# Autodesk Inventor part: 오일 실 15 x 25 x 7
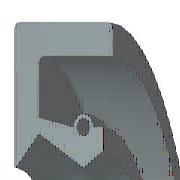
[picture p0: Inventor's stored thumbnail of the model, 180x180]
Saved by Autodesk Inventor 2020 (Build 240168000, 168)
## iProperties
Created: 2012-02
Part Number: 오일 실 15 x 25 x 7
Material: 고무
Description: 오일-실
Document SubType Name: Modeling
Standard: KS B 2804
Designer: mduedu
Standards Organization: KS
Language: ko-KR
Size Designation: D - 15 25 7
Categories: <MemberInstance><Categories><Category DisplayName="샤프트 부품" InternalName="7f7aeb1f-a693-4053-b835-cee3144e0d98" Mnemonic="SHFT"><Category DisplayName="실링" Intern
Density: 0.93 g/cm^3
Appearance: 고무 - 검은색 - 버전 1.1
IsCustomPart: 1
Author: mduedu
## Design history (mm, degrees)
revolve "본체" stored, may be unused: angle "d17" = 90 deg
revolve "스프링1" stored, may be unused: angle "d18" = 90 deg
body "Solid1"
sketch "스케치1"
  geometry: L1 (0, 12.5)-(7, 12.5); L2 (7, 10.75)-(1.75, 10.75); L3 (1.75, 9.25)-(4.9, 7.5); L4 (4.9, 7.5)-(0, 7.5); L5 (0, 0)-(9.586, 0) reference; L6 (4.9, 7.5)-(6.3, 8.375); L7 (0, 18)-(0, -3) reference; L8 (-1.941, 0)-(11.507, 0) reference; L9 (4.2, 9.6)-(1.75, 10.09); L10 (1.75, 10.09)-(1.75, 10.75); L11 (0, 12.5)-(0, 7.588); L12 (4.9, 7.5)-(0, 7.5); L13 (1.75, 9.25)-(0.152, 7.528); L14 (7, 12.5)-(7, 10.75); L15 (5.6, 9.6)-(6.3, 9.6); L16 (6.3, 9.6)-(6.3, 8.375); C1 r 0.455 at (4.9, 9.6); A1 r 0.7 centre (4.9, 9.6) between (5.6, 9.6) and (4.2, 9.6); A2 r 0.088 centre (0.088, 7.588) between (0, 7.588) and (0.152, 7.528); 1 further point
  constraints: 28 end point, 5 horizontal alignment, 5 point on line, 4 point on circle, 4 vertical alignment, 3 centre point, 3 tangent, 2 collinear, 2 horizontal, 2 perpendicular, 1 coincident, 1 parallel
  dimensions: "d0" = 25 diameter of L1 L5 (= SD2); "d1" = 1.75 distance of L1.end L2.start (= SD); "d2" = 0.91 diameter of C1 (= SPDI); "d3" = 1.4 diameter of A1 (= SPDA); "d4" = 15 diameter of L3.end L5 (= NND); "d5" = 18.5 diameter of L3.start L5 (= TKDM); "d7" = 20.18 diameter of L9.end L5 (= TKDM + 0.24 x SWDT); "d8" = 1.75 distance between parallel lines of L11 L10 (= SD); "d9" = 4.9 distance from line of L11 C1.centre (= SPDST); "d10" = 19.2 diameter of C1.centre L5 (= HLDM); "d11" = 0.0875 radius of A2 (= 0.25 x LAB); "d12" = 6.3 distance between parallel lines of L11 L16 (= SDI); "d13" = 16.75 diameter of L6.end L5 (= ABDM); "d14" = 7 distance from line of L11 L1.end (= SWDT)
fillet "모깎기1" dims "d6" = 0.3 (= RR)
other parameters: "SD2" = 25 [user parameter; used in 1 equation term], "SWDT" = 7 [user parameter; used in 2 equation terms], "RR" = 0.3 [user parameter; used in 1 equation term], "SD" = 1.75 [user parameter; used in 2 equation terms], "NND" = 15 [user parameter; used in 1 equation term], "SPDA" = 1.4 [user parameter; used in 1 equation term], "SPDI" = 0.91 [user parameter; used in 1 equation term], "TKDM" = 18.5 [user parameter; used in 2 equation terms], "HLDM" = 19.2 [user parameter; used in 1 equation term], "ABDM" = 16.75 [user parameter; used in 1 equation term], "SDI" = 6.3 [user parameter; used in 1 equation term], "SPDST" = 4.9 [user parameter; used in 1 equation term], "LAB" = 0.35 [user parameter; used in 1 equation term], "d15" = 0, "d16" = 0, "d19" = 0
